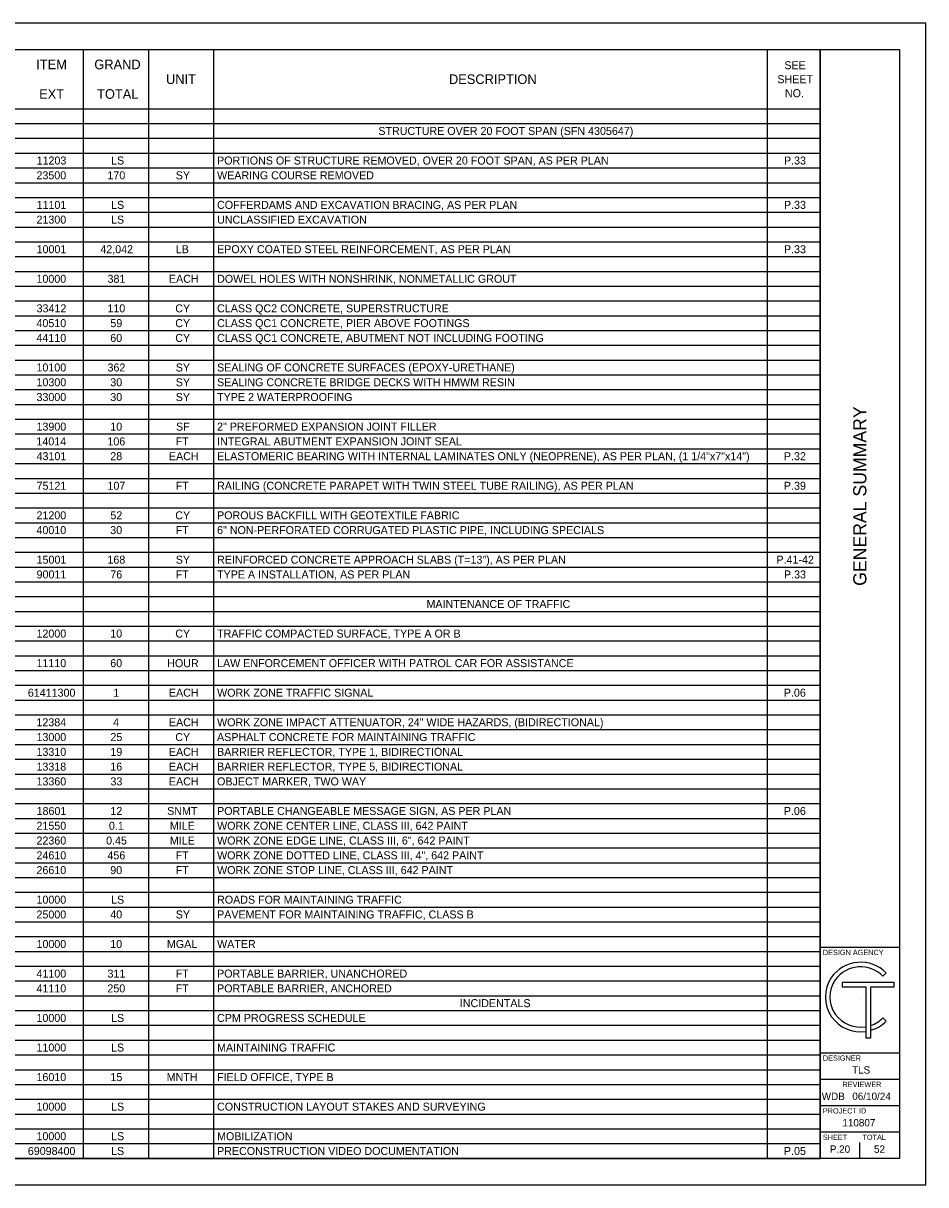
# Model space of a CAD drawing. Extents: x 0 to 34, y 0 to 22.
# Drawn here: x 16.9 to 34, y 0 to 22 of the extents above; entities that cross this region are included whole.
import ezdxf

# ---------------------------------------------------------------- set-up
doc = ezdxf.new("R2010")
doc.units = 0
for name, color, linetype in [('Default', 7, 'Continuous'), ('SH_Border', 7, 'Continuous'), ('SH_Cut_Line', 7, 'Continuous'), ('SH_Data', 7, 'Continuous'), ('SH_Text', 7, 'Continuous')]:
    doc.layers.add(name, color=color, linetype=linetype)

msp = doc.modelspace()

# ---------------------------------------------------------------- linework, layer by layer
at = {"layer": 'Default'}
for p, q in [((1.5, 21.5), (32, 21.5)), ((18.035, 21.5), (18.035, 0.5)), ((19.27, 21.5), (19.27, 0.5)), ((20.505, 21.5), (20.505, 0.5)), ((30.995, 21.5), (30.995, 0.5)), ((32, 21.5), (32, 0.5)), ((1.5, 20.38), (32, 20.38)), ((1.5, 20.1), (32, 20.1)), ((1.5, 19.82), (32, 19.82)), ((1.5, 19.54), (32, 19.54)), ((1.5, 19.26), (32, 19.26)), ((1.5, 18.98), (32, 18.98)), ((1.5, 18.7), (32, 18.7)), ((1.5, 18.42), (32, 18.42)), ((1.5, 18.14), (32, 18.14)), ((1.5, 17.86), (32, 17.86)), ((1.5, 17.58), (32, 17.58)), ((1.5, 17.3), (32, 17.3)), ((1.5, 17.02), (32, 17.02)), ((1.5, 16.74), (32, 16.74)), ((1.5, 16.46), (32, 16.46)), ((1.5, 16.18), (32, 16.18)), ((1.5, 15.9), (32, 15.9)), ((1.5, 15.62), (32, 15.62)), ((1.5, 15.34), (32, 15.34)), ((1.5, 15.06), (32, 15.06)), ((1.5, 14.78), (32, 14.78)), ((1.5, 14.5), (32, 14.5)), ((1.5, 14.22), (32, 14.22)), ((1.5, 13.94), (32, 13.94)), ((1.5, 13.66), (32, 13.66)), ((1.5, 13.38), (32, 13.38)), ((1.5, 13.1), (32, 13.1)), ((1.5, 12.82), (32, 12.82)), ((1.5, 12.54), (32, 12.54)), ((1.5, 12.26), (32, 12.26)), ((1.5, 11.98), (32, 11.98)), ((1.5, 11.7), (32, 11.7)), ((1.5, 11.42), (32, 11.42)), ((1.5, 11.14), (32, 11.14)), ((1.5, 10.86), (32, 10.86)), ((1.5, 10.58), (32, 10.58)), ((1.5, 10.3), (32, 10.3)), ((1.5, 10.02), (32, 10.02)), ((1.5, 9.74), (32, 9.74)), ((1.5, 9.46), (32, 9.46)), ((1.5, 9.18), (32, 9.18)), ((1.5, 8.9), (32, 8.9)), ((1.5, 8.62), (32, 8.62)), ((1.5, 8.34), (32, 8.34)), ((1.5, 8.06), (32, 8.06)), ((1.5, 7.78), (32, 7.78)), ((1.5, 7.5), (32, 7.5)), ((1.5, 7.22), (32, 7.22)), ((1.5, 6.94), (32, 6.94)), ((1.5, 6.66), (32, 6.66)), ((1.5, 6.38), (32, 6.38)), ((1.5, 6.1), (32, 6.1)), ((1.5, 5.82), (32, 5.82)), ((1.5, 5.54), (32, 5.54)), ((1.5, 5.26), (32, 5.26)), ((1.5, 4.98), (32, 4.98)), ((1.5, 4.7), (32, 4.7)), ((1.5, 4.42), (32, 4.42)), ((1.5, 4.14), (32, 4.14)), ((1.5, 3.86), (32, 3.86)), ((1.5, 3.58), (32, 3.58)), ((1.5, 3.3), (32, 3.3)), ((1.5, 3.02), (32, 3.02)), ((1.5, 2.74), (32, 2.74)), ((1.5, 2.46), (32, 2.46)), ((1.5, 2.18), (32, 2.18)), ((1.5, 1.9), (32, 1.9)), ((1.5, 1.62), (32, 1.62)), ((1.5, 1.34), (32, 1.34)), ((1.5, 1.06), (32, 1.06)), ((1.5, 0.78), (32, 0.78)), ((1.5, 0.5), (32, 0.5))]:
    msp.add_line(p, q, dxfattribs=at)
at = {"layer": 'SH_Border'}
for p, q in [((32, 0.5), (32, 21.5)), ((32, 4.5), (33.5, 4.5)), ((32, 2.5), (33.5, 2.5)), ((32, 2), (33.5, 2)), ((32, 1.5), (33.5, 1.5)), ((32, 1), (33.5, 1))]:
    msp.add_line(p, q, dxfattribs=at)
msp.add_lwpolyline([(1.5, 21.5), (33.5, 21.5), (33.5, 0.5), (1.5, 0.5)], close=True, dxfattribs=at)
at = {"layer": 'SH_Cut_Line'}
msp.add_lwpolyline([(0, 0), (34, 0), (34, 22), (0, 22)], close=True, dxfattribs=at)
at = {"layer": 'SH_Data'}
for p, q in [((32.75, 3.5), (32.75, 3.5)), ((32.375, 0.675), (32.375, 0.675)), ((32.75, 0.5), (32.75, 0.8))]:
    msp.add_line(p, q, dxfattribs=at)
at = {"layer": 'SH_Text'}
for p, q in [((33.249, 4.013), (33.187, 3.952)), ((33.249, 4.013), (33.187, 3.952)), ((33.402, 3.833), (32.414, 3.833)), ((32.414, 3.833), (32.414, 3.751)), ((32.414, 3.751), (32.863, 3.751)), ((32.863, 3.751), (32.863, 2.785)), ((32.956, 2.785), (32.956, 3.751)), ((32.956, 3.751), (33.402, 3.751)), ((33.402, 3.751), (33.402, 3.833)), ((33.187, 3.16), (33.249, 3.099)), ((33.187, 3.16), (33.249, 3.099)), ((32.863, 2.993), (32.863, 2.905)), ((32.863, 2.993), (32.863, 2.905)), ((32.956, 2.925), (32.956, 3.016)), ((32.956, 2.925), (32.956, 3.016)), ((32.863, 2.785), (32.956, 2.785))]:
    msp.add_line(p, q, dxfattribs=at)
msp.add_lwpolyline([(32.863, 3.751), (32.863, 2.785), (32.956, 2.785), (32.956, 3.751), (33.402, 3.751), (33.402, 3.833), (32.414, 3.833), (32.414, 3.751)], close=True, dxfattribs=at)
for centre, radius, start, end in [((32.766, 3.535), 0.68, 44.7027, 144.3276), ((32.766, 3.535), 0.68, 44.7027, 144.3276), ((32.766, 3.535), 0.593, 44.7362, 144.1102), ((32.766, 3.535), 0.593, 44.7362, 144.1102), ((32.764, 3.556), 0.666, 145.7329, 214.2671), ((32.764, 3.556), 0.666, 145.7329, 214.2671), ((32.764, 3.556), 0.579, 145.7266, 214.2734), ((32.764, 3.556), 0.579, 145.7266, 214.2734), ((32.766, 3.578), 0.68, 215.6724, 278.2613), ((32.766, 3.578), 0.68, 215.6724, 278.2613), ((32.766, 3.578), 0.593, 215.8898, 279.4882), ((32.766, 3.578), 0.593, 215.8898, 279.4882), ((32.766, 3.578), 0.593, 288.6992, 315.2638), ((32.766, 3.578), 0.593, 288.6992, 315.2638), ((32.766, 3.578), 0.68, 286.2291, 315.2973), ((32.766, 3.578), 0.68, 286.2291, 315.2973)]:
    msp.add_arc(centre, radius, start, end, dxfattribs=at)

# ---------------------------------------------------------------- texts
at = {"layer": 'Default'}
for s, height, p in [('ITEM', 0.1818, (17.145, 21.129)), ('GRAND', 0.1818, (18.245, 21.129)), ('SEE ', 0.1515, (31.32, 21.129)), ('UNIT', 0.1818, (19.604, 20.849)), ('DESCRIPTION', 0.18184, (24.965, 20.849)), ('SHEET ', 0.1515, (31.187, 20.864)), ('EXT', 0.1818, (17.199, 20.569)), ('TOTAL', 0.1818, (18.297, 20.569)), ('NO.', 0.1515, (31.331, 20.599)), ('STRUCTURE OVER 20 FOOT SPAN (SFN 4305647)', 0.15153, (23.627, 19.884)), ('11203', 0.1515, (17.151, 19.324)), ('LS', 0.1515, (18.562, 19.324)), ('PORTIONS OF STRUCTURE REMOVED, OVER 20 FOOT SPAN, AS PER PLAN', 0.15153, (20.571, 19.324)), ('P.33', 0.1515, (31.313, 19.324)), ('23500', 0.1515, (17.149, 19.044)), ('170', 0.1515, (18.493, 19.044)), ('SY', 0.1515, (19.788, 19.044)), ('WEARING COURSE REMOVED', 0.15153, (20.571, 19.044)), ('11101', 0.1515, (17.151, 18.484)), ('LS', 0.1515, (18.562, 18.484)), ('COFFERDAMS AND EXCAVATION BRACING, AS PER PLAN', 0.15153, (20.571, 18.484)), ('P.33', 0.1515, (31.313, 18.484)), ('21300', 0.1515, (17.149, 18.204)), ('LS', 0.1515, (18.562, 18.204)), ('UNCLASSIFIED EXCAVATION', 0.15153, (20.571, 18.204)), ('10001', 0.1515, (17.151, 17.644)), ('42,042', 0.1515, (18.359, 17.644)), ('LB', 0.1515, (19.788, 17.644)), ('EPOXY COATED STEEL REINFORCEMENT, AS PER PLAN', 0.15153, (20.571, 17.644)), ('P.33', 0.1515, (31.313, 17.644)), ('10000', 0.1515, (17.149, 17.084)), ('381', 0.1515, (18.495, 17.084)), ('EACH', 0.1515, (19.659, 17.084)), ('DOWEL HOLES WITH NONSHRINK, NONMETALLIC GROUT', 0.15153, (20.571, 17.084)), ('33412', 0.1515, (17.151, 16.524)), ('110', 0.1515, (18.493, 16.524)), ('CY', 0.1515, (19.779, 16.524)), ('CLASS QC2 CONCRETE, SUPERSTRUCTURE', 0.15153, (20.571, 16.524)), ('40510', 0.1515, (17.149, 16.244)), ('59', 0.1515, (18.549, 16.244)), ('CY', 0.1515, (19.779, 16.244)), ('CLASS QC1 CONCRETE, PIER ABOVE FOOTINGS', 0.15153, (20.571, 16.244)), ('44110', 0.1515, (17.149, 15.964)), ('60', 0.1515, (18.547, 15.964)), ('CY', 0.1515, (19.779, 15.964)), ('CLASS QC1 CONCRETE, ABUTMENT NOT INCLUDING FOOTING', 0.15153, (20.571, 15.964)), ('10100', 0.1515, (17.149, 15.404)), ('362', 0.1515, (18.495, 15.404)), ('SY', 0.1515, (19.788, 15.404)), ('SEALING OF CONCRETE SURFACES (EPOXY-URETHANE)', 0.15153, (20.571, 15.404)), ('10300', 0.1515, (17.149, 15.124)), ('30', 0.1515, (18.547, 15.124)), ('SY', 0.1515, (19.788, 15.124)), ('SEALING CONCRETE BRIDGE DECKS WITH HMWM RESIN', 0.15153, (20.571, 15.124)), ('33000', 0.1515, (17.149, 14.844)), ('30', 0.1515, (18.547, 14.844)), ('SY', 0.1515, (19.788, 14.844)), ('TYPE 2 WATERPROOFING', 0.15153, (20.571, 14.844)), ('13900', 0.1515, (17.149, 14.284)), ('10', 0.1515, (18.547, 14.284)), ('SF', 0.1515, (19.793, 14.284)), ('2" PREFORMED EXPANSION JOINT FILLER', 0.15153, (20.571, 14.284)), ('14014', 0.1515, (17.148, 14.004)), ('106', 0.1515, (18.493, 14.004)), ('FT', 0.1515, (19.786, 14.004)), ('INTEGRAL ABUTMENT EXPANSION JOINT SEAL', 0.15153, (20.571, 14.004)), ('43101', 0.1515, (17.151, 13.724)), ('28', 0.1515, (18.548, 13.724)), ('EACH', 0.1515, (19.659, 13.724)), ('ELASTOMERIC BEARING WITH INTERNAL LAMINATES ONLY (NEOPRENE), AS PER PLAN, (1 1/4"x7"x14")', 0.15153, (20.571, 13.724)), ('P.32', 0.1515, (31.312, 13.724)), ('75121', 0.1515, (17.151, 13.164)), ('107', 0.1515, (18.494, 13.164)), ('FT', 0.1515, (19.786, 13.164)), ('RAILING (CONCRETE PARAPET WITH TWIN STEEL TUBE RAILING), AS PER PLAN', 0.15153, (20.571, 13.164)), ('P.39', 0.1515, (31.312, 13.164)), ('21200', 0.1515, (17.149, 12.604)), ('52', 0.1515, (18.549, 12.604)), ('CY', 0.1515, (19.779, 12.604)), ('POROUS BACKFILL WITH GEOTEXTILE FABRIC', 0.15153, (20.571, 12.604)), ('40010', 0.1515, (17.149, 12.324)), ('30', 0.1515, (18.547, 12.324)), ('FT', 0.1515, (19.786, 12.324)), ('6" NON-PERFORATED CORRUGATED PLASTIC PIPE, INCLUDING SPECIALS', 0.15153, (20.571, 12.324)), ('15001', 0.1515, (17.151, 11.764)), ('168', 0.1515, (18.493, 11.764)), ('SY', 0.1515, (19.788, 11.764)), ('REINFORCED CONCRETE APPROACH SLABS (T=13"), AS PER PLAN', 0.15153, (20.571, 11.764)), ('P.41-42', 0.1515, (31.17, 11.764)), ('90011', 0.1515, (17.151, 11.484)), ('76', 0.1515, (18.548, 11.484)), ('FT', 0.1515, (19.786, 11.484)), ('TYPE A INSTALLATION, AS PER PLAN', 0.15153, (20.571, 11.484)), ('P.33', 0.1515, (31.313, 11.484)), ('MAINTENANCE OF TRAFFIC', 0.15153, (24.539, 10.924)), ('12000', 0.1515, (17.149, 10.364)), ('10', 0.1515, (18.547, 10.364)), ('CY', 0.1515, (19.779, 10.364)), ('TRAFFIC COMPACTED SURFACE, TYPE A OR B', 0.15153, (20.571, 10.364)), ('11110', 0.1515, (17.149, 9.804)), ('60', 0.1515, (18.547, 9.804)), ('HOUR', 0.1515, (19.626, 9.804)), ('LAW ENFORCEMENT OFFICER WITH PATROL CAR FOR ASSISTANCE', 0.15153, (20.571, 9.804)), ('61411300', 0.1515, (16.985, 9.244)), ('1', 0.152, (18.604, 9.244)), ('EACH', 0.1515, (19.659, 9.244)), ('WORK ZONE TRAFFIC SIGNAL', 0.15153, (20.571, 9.244)), ('P.06', 0.1515, (31.31, 9.244)), ('12384', 0.1515, (17.148, 8.684)), ('4', 0.152, (18.601, 8.684)), ('EACH', 0.1515, (19.659, 8.684)), ('WORK ZONE IMPACT ATTENUATOR, 24" WIDE HAZARDS, (BIDIRECTIONAL)', 0.15153, (20.571, 8.684)), ('13000', 0.1515, (17.149, 8.404)), ('25', 0.1515, (18.55, 8.404)), ('CY', 0.1515, (19.779, 8.404)), ('ASPHALT CONCRETE FOR MAINTAINING TRAFFIC', 0.15153, (20.571, 8.404)), ('13310', 0.1515, (17.149, 8.124)), ('19', 0.1515, (18.549, 8.124)), ('EACH', 0.1515, (19.659, 8.124)), ('BARRIER REFLECTOR, TYPE 1, BIDIRECTIONAL', 0.15153, (20.571, 8.124)), ('13318', 0.1515, (17.149, 7.844)), ('16', 0.1515, (18.548, 7.844)), ('EACH', 0.1515, (19.659, 7.844)), ('BARRIER REFLECTOR, TYPE 5, BIDIRECTIONAL', 0.15153, (20.571, 7.844)), ('13360', 0.1515, (17.149, 7.564)), ('33', 0.1515, (18.55, 7.564)), ('EACH', 0.1515, (19.659, 7.564)), ('OBJECT MARKER, TWO WAY', 0.15153, (20.571, 7.564)), ('18601', 0.1515, (17.151, 7.004)), ('12', 0.1515, (18.549, 7.004)), ('SNMT', 0.1515, (19.625, 7.004)), ('PORTABLE CHANGEABLE MESSAGE SIGN, AS PER PLAN', 0.15153, (20.571, 7.004)), ('P.06', 0.1515, (31.31, 7.004)), ('21550', 0.1515, (17.149, 6.724)), ('0.1', 0.1515, (18.522, 6.724)), ('MILE', 0.1515, (19.676, 6.724)), ('WORK ZONE CENTER LINE, CLASS III, 642 PAINT', 0.15153, (20.571, 6.724)), ('22360', 0.1515, (17.149, 6.444)), ('0.45', 0.1515, (18.468, 6.444)), ('MILE', 0.1515, (19.676, 6.444)), ('WORK ZONE EDGE LINE, CLASS III, 6", 642 PAINT', 0.15153, (20.571, 6.444)), ('24610', 0.1515, (17.149, 6.164)), ('456', 0.1515, (18.493, 6.164)), ('FT', 0.1515, (19.786, 6.164)), ('WORK ZONE DOTTED LINE, CLASS III, 4", 642 PAINT', 0.15153, (20.571, 6.164)), ('26610', 0.1515, (17.149, 5.884)), ('90', 0.1515, (18.547, 5.884)), ('FT', 0.1515, (19.786, 5.884)), ('WORK ZONE STOP LINE, CLASS III, 642 PAINT', 0.15153, (20.571, 5.884)), ('10000', 0.1515, (17.149, 5.324)), ('LS', 0.1515, (18.562, 5.324)), ('ROADS FOR MAINTAINING TRAFFIC', 0.15153, (20.571, 5.324)), ('25000', 0.1515, (17.149, 5.044)), ('40', 0.1515, (18.547, 5.044)), ('SY', 0.1515, (19.788, 5.044)), ('PAVEMENT FOR MAINTAINING TRAFFIC, CLASS B', 0.15153, (20.571, 5.044)), ('10000', 0.1515, (17.149, 4.484)), ('10', 0.1515, (18.547, 4.484)), ('MGAL', 0.1515, (19.621, 4.484)), ('WATER', 0.1515, (20.571, 4.484)), ('41100', 0.1515, (17.149, 3.924)), ('311', 0.1515, (18.495, 3.924)), ('FT', 0.1515, (19.786, 3.924)), ('PORTABLE BARRIER, UNANCHORED', 0.15153, (20.571, 3.924)), ('41110', 0.1515, (17.149, 3.644)), ('250', 0.1515, (18.493, 3.644)), ('FT', 0.1515, (19.786, 3.644)), ('PORTABLE BARRIER, ANCHORED', 0.15153, (20.571, 3.644)), ('INCIDENTALS', 0.15153, (25.171, 3.364)), ('10000', 0.1515, (17.149, 3.084)), ('LS', 0.1515, (18.562, 3.084)), ('CPM PROGRESS SCHEDULE', 0.15153, (20.571, 3.084)), ('11000', 0.1515, (17.149, 2.524)), ('LS', 0.1515, (18.562, 2.524)), ('MAINTAINING TRAFFIC', 0.15153, (20.571, 2.524)), ('16010', 0.1515, (17.149, 1.964)), ('15', 0.1515, (18.55, 1.964)), ('MNTH', 0.1515, (19.616, 1.964)), ('FIELD OFFICE, TYPE B', 0.15153, (20.571, 1.964)), ('10000', 0.1515, (17.149, 1.404)), ('LS', 0.1515, (18.562, 1.404)), ('CONSTRUCTION LAYOUT STAKES AND SURVEYING', 0.15153, (20.571, 1.404)), ('10000', 0.1515, (17.149, 0.844)), ('LS', 0.1515, (18.562, 0.844)), ('MOBILIZATION', 0.15153, (20.571, 0.844)), ('69098400', 0.1515, (16.985, 0.564)), ('LS', 0.1515, (18.562, 0.564)), ('PRECONSTRUCTION VIDEO DOCUMENTATION', 0.15153, (20.571, 0.564)), ('P.05', 0.1515, (31.312, 0.564))]:
    msp.add_text(s, height=height, dxfattribs=at).set_placement(p)
at = {"layer": 'SH_Data'}
msp.add_text('GENERAL SUMMARY', height=0.25, rotation=90, dxfattribs=at).set_placement((32.875, 11.344))
for s, height, p in [('DESIGN AGENCY', 0.1, (32.05, 4.35)), ('DESIGNER', 0.1, (32.05, 2.35)), ('TLS', 0.14, (32.603, 2.105)), ('REVIEWER', 0.1, (32.422, 1.85)), ('WDB', 0.14, (32.029, 1.605)), ('06/10/24', 0.14, (32.608, 1.605)), ('PROJECT ID', 0.1, (32.05, 1.35)), ('110807', 0.14, (32.42, 1.105)), ('SHEET', 0.1, (32.05, 0.85)), ('TOTAL', 0.1, (32.8, 0.85)), ('P.20', 0.14, (32.182, 0.605)), ('52', 0.14, (33.019, 0.605))]:
    msp.add_text(s, height=height, dxfattribs=at).set_placement(p)

doc.saveas('drawing.dxf')
